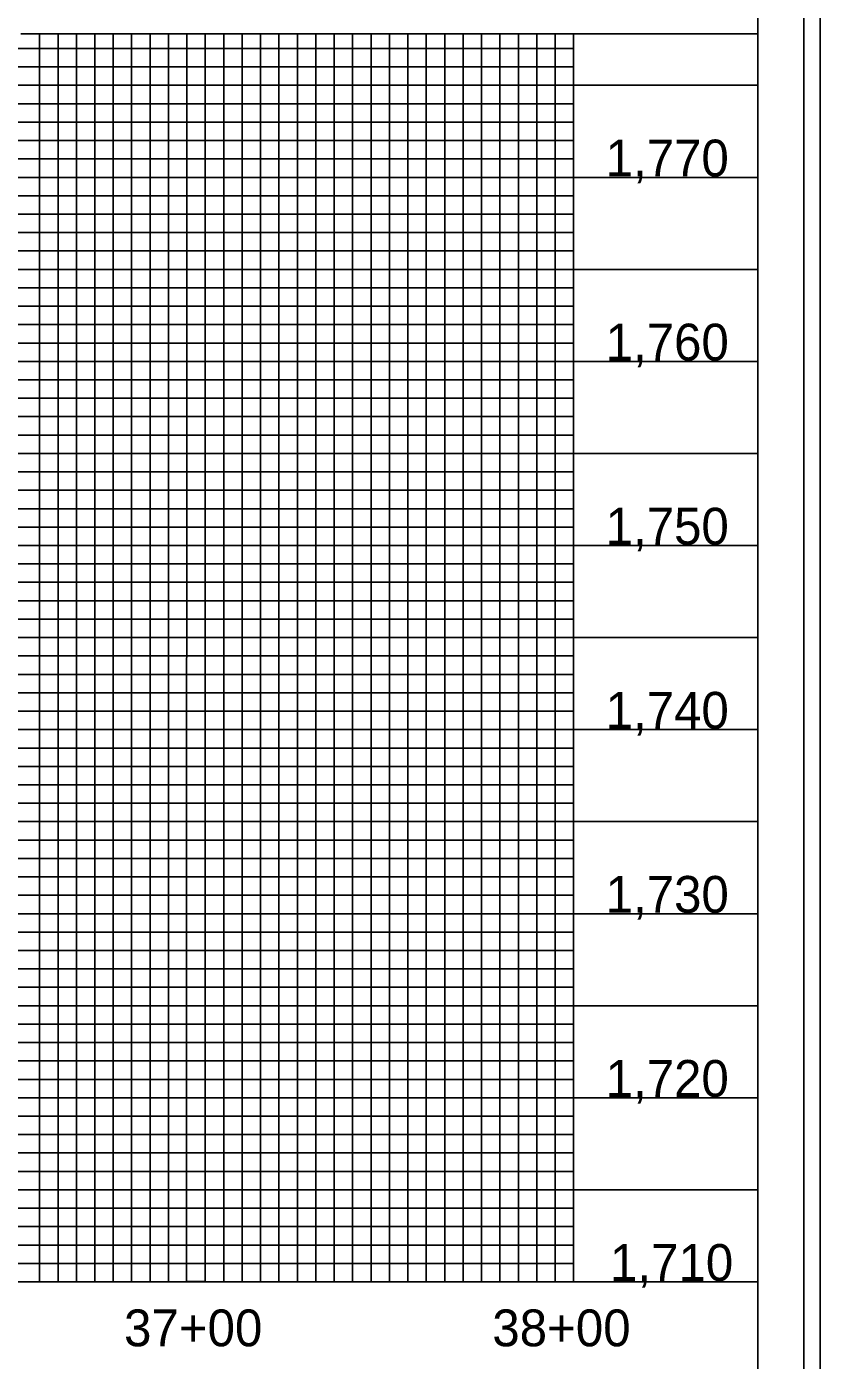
# Model space of a CAD drawing. Extents: x 497599 to 513368, y 404140 to 476034.
# Drawn here: x 507160.2 to 507375.7, y 439314.8 to 439677.1 of the extents above; entities that cross this region are included whole.
import ezdxf

# ---------------------------------------------------------------- set-up
doc = ezdxf.new("R2010")
doc.units = 0
for name, color, linetype in [('Exist Vertical Profile Vertical Axis Label', 7, 'Continuous'), ('Sheet DOT Grid CELL', 7, 'Continuous'), ('Sheet Plot Border Inside CELL', 7, 'Continuous'), ('Sheet Plot Border Outside CELL', 7, 'Continuous'), ('Sheet Profile CELL', 7, 'Continuous'), ('Sheet Profile Grid Major CELL', 7, 'Continuous'), ('Sheet Profile Grid Middle CELL', 7, 'Continuous'), ('Sheet Profile Grid Minor CELL', 7, 'Continuous'), ('Sheet Sticker Exception Certification CELL', 7, 'Continuous')]:
    doc.layers.add(name, color=color, linetype=linetype)

msp = doc.modelspace()

# ---------------------------------------------------------------- linework, layer by layer
at = {"layer": 'Sheet DOT Grid CELL'}
for p, q in [((507208.68, 439336.14), (507208.68, 439675.09)), ((507258.68, 439336.14), (507258.68, 439675.09)), ((507308.68, 439336.14), (507308.68, 439675.09)), ((507358.68, 439636.14), (505858.68, 439636.14)), ((507358.68, 439586.14), (505858.68, 439586.14)), ((507358.68, 439536.14), (505858.68, 439536.14)), ((507358.68, 439486.14), (505858.68, 439486.14)), ((507358.68, 439436.14), (505858.68, 439436.14)), ((507358.68, 439386.14), (505858.68, 439386.14))]:
    msp.add_line(p, q, dxfattribs=at)
at = {"layer": 'Sheet Plot Border Inside CELL'}
msp.add_lwpolyline([(505704.68, 438783.59), (507371.18, 438783.59), (507371.18, 439838.69), (505704.68, 439838.69)], close=True, dxfattribs=at)
at = {"layer": 'Sheet Plot Border Outside CELL'}
msp.add_lwpolyline([(505691.68, 438761.14), (507375.68, 438761.14), (507375.68, 439861.14), (505691.68, 439861.14)], close=True, dxfattribs=at)
at = {"layer": 'Sheet Profile CELL'}
msp.add_line((505858.68, 439336.14), (507358.68, 439336.14), dxfattribs=at)
msp.add_lwpolyline([(507358.68, 439836.14), (505858.68, 439836.14), (505858.68, 438786.14), (507358.68, 438786.14)], close=True, dxfattribs=at)
at = {"layer": 'Sheet Profile Grid Major CELL'}
for points in [[(507308.68, 439675.09), (507308.68, 439336.14), (507358.68, 439336.14), (507358.68, 439686.14)], [(507208.68, 439675.09), (507208.68, 439336.14), (507258.68, 439336.14), (507258.68, 439336.14), (507258.68, 439675.09)], [(507358.68, 439636.14), (505858.68, 439636.14), (505858.68, 439586.14), (507358.68, 439586.14)], [(507358.68, 439536.14), (505858.68, 439536.14), (505858.68, 439486.14), (507358.68, 439486.14)], [(507358.68, 439436.14), (505858.68, 439436.14), (505858.68, 439436.14), (505858.68, 439386.14), (507358.68, 439386.14)]]:
    msp.add_lwpolyline(points, dxfattribs=at)
at = {"layer": 'Sheet Profile Grid Middle CELL'}
for points in [[(506683.68, 439836.14), (506733.68, 439836.14), (506733.68, 439336.14), (506783.68, 439336.14), (506783.68, 439836.14), (506833.68, 439836.14), (506833.68, 439336.14), (506883.68, 439336.14), (506883.68, 439836.14), (506933.68, 439836.14), (506933.68, 439336.14), (506983.68, 439336.14), (506983.68, 439836.14), (507033.68, 439836.14), (507033.68, 439336.14), (507083.68, 439336.14), (507083.68, 439836.14), (507133.68, 439836.14), (507133.68, 439336.14), (507183.68, 439336.14), (507183.68, 439675.09)], [(507183.68, 439598.94), (507183.68, 439336.14), (507233.68, 439336.14), (507233.68, 439675.09)], [(507233.68, 439598.94), (507233.68, 439336.14), (507283.68, 439336.14), (507283.68, 439675.09)], [(507358.68, 439661.14), (505858.68, 439661.14), (505858.68, 439611.14), (507183.68, 439611.14)], [(507183.68, 439611.14), (507358.68, 439611.14)], [(507358.68, 439561.14), (505858.68, 439561.14), (505858.68, 439511.14), (507358.68, 439511.14)], [(507358.68, 439461.14), (505858.68, 439461.14), (505858.68, 439411.14), (507358.68, 439411.14)], [(507358.68, 439361.14), (505858.68, 439361.14)]]:
    msp.add_lwpolyline(points, dxfattribs=at)
at = {"layer": 'Sheet Profile Grid Minor CELL'}
for p, q in [((505908.68, 439671.14), (507308.68, 439671.14)), ((507308.68, 439651.14), (505908.68, 439651.14)), ((505908.68, 439646.14), (507308.68, 439646.14)), ((507308.68, 439626.14), (505908.68, 439626.14)), ((505908.68, 439621.14), (507308.68, 439621.14)), ((507308.68, 439601.14), (505908.68, 439601.14)), ((505908.68, 439596.14), (507308.68, 439596.14)), ((507308.68, 439591.14), (505908.68, 439591.14)), ((505908.68, 439581.14), (507308.68, 439581.14)), ((507308.68, 439576.14), (505908.68, 439576.14)), ((505908.68, 439571.14), (507308.68, 439571.14)), ((507308.68, 439566.14), (505908.68, 439566.14)), ((505908.68, 439556.14), (507308.68, 439556.14)), ((507308.68, 439551.14), (505908.68, 439551.14)), ((505908.68, 439546.14), (507308.68, 439546.14)), ((507308.68, 439541.14), (505908.68, 439541.14)), ((505908.68, 439531.14), (507308.68, 439531.14)), ((507308.68, 439526.14), (505908.68, 439526.14)), ((505908.68, 439521.14), (507308.68, 439521.14)), ((507308.68, 439516.14), (505908.68, 439516.14)), ((505908.68, 439506.14), (507308.68, 439506.14)), ((507308.68, 439501.14), (505908.68, 439501.14)), ((505908.68, 439496.14), (507308.68, 439496.14)), ((507308.68, 439491.14), (505908.68, 439491.14)), ((505908.68, 439481.14), (507308.68, 439481.14)), ((507308.68, 439476.14), (505908.68, 439476.14)), ((505908.68, 439471.14), (507308.68, 439471.14)), ((507308.68, 439466.14), (505908.68, 439466.14)), ((505908.68, 439456.14), (507308.68, 439456.14)), ((507308.68, 439451.14), (505908.68, 439451.14)), ((507308.68, 439446.14), (505908.68, 439446.14)), ((507308.68, 439441.14), (505908.68, 439441.14)), ((505908.68, 439431.14), (507308.68, 439431.14)), ((507308.68, 439426.14), (505908.68, 439426.14)), ((505908.68, 439421.14), (507308.68, 439421.14)), ((507308.68, 439416.14), (505908.68, 439416.14)), ((505908.68, 439406.14), (507308.68, 439406.14)), ((507308.68, 439401.14), (505908.68, 439401.14)), ((505908.68, 439396.14), (507308.68, 439396.14)), ((507308.68, 439391.14), (505908.68, 439391.14)), ((505908.68, 439381.14), (507308.68, 439381.14)), ((507308.68, 439376.14), (505908.68, 439376.14)), ((505908.68, 439371.14), (507308.68, 439371.14)), ((507308.68, 439366.14), (505908.68, 439366.14)), ((505908.68, 439356.14), (507308.68, 439356.14)), ((507308.68, 439351.14), (505908.68, 439351.14)), ((505908.68, 439346.14), (507308.68, 439346.14))]:
    msp.add_line(p, q, dxfattribs=at)
for points in [[(507163.68, 439675.09), (507163.68, 439336.14), (507168.68, 439336.14), (507168.68, 439675.09)], [(507173.68, 439675.09), (507173.68, 439336.14), (507178.68, 439336.14), (507178.68, 439675.09)], [(507188.68, 439675.09), (507188.68, 439336.14), (507188.68, 439336.14), (507193.68, 439336.14), (507198.68, 439336.14), (507198.68, 439675.09)], [(507193.68, 439675.09), (507193.68, 439336.14)], [(507203.67, 439675.09), (507203.58, 439336.19), (507208.58, 439336.19), (507213.68, 439336.14), (507213.68, 439675.09)], [(507213.68, 439598.94), (507213.68, 439336.14), (507218.68, 439336.14), (507218.68, 439675.09)], [(507223.68, 439675.09), (507223.68, 439336.14), (507228.68, 439336.14), (507228.68, 439675.09)], [(507238.68, 439675.09), (507238.68, 439336.14), (507243.68, 439336.14), (507243.68, 439675.09)], [(507248.68, 439675.09), (507248.68, 439336.14), (507253.68, 439336.14), (507253.68, 439675.09)], [(507263.68, 439675.09), (507263.68, 439336.14), (507268.68, 439336.14), (507268.68, 439675.09)], [(507273.68, 439675.09), (507273.68, 439336.14), (507278.68, 439336.14), (507278.68, 439675.09)], [(507288.68, 439675.09), (507288.68, 439336.14), (507293.68, 439336.14), (507293.68, 439675.09)], [(507298.68, 439675.09), (507298.68, 439336.14), (507303.68, 439336.14), (507303.68, 439675.09)], [(507308.68, 439666.14), (505908.68, 439666.14), (505908.68, 439656.14), (507308.68, 439656.14)], [(507308.68, 439641.14), (505908.68, 439641.14), (505908.68, 439631.14), (507308.68, 439631.14)], [(507308.68, 439616.14), (505908.68, 439616.14), (505908.68, 439606.14), (507308.68, 439606.14)], [(507308.68, 439341.14), (505908.68, 439341.14)]]:
    msp.add_lwpolyline(points, dxfattribs=at)
at = {"layer": 'Sheet Sticker Exception Certification CELL'}
for p, q in [((507358.67, 439698.58), (507358.67, 439675.08)), ((507358.67, 439698.58), (507358.67, 439675.08)), ((507358.67, 439675.09), (507158.63, 439675.09)), ((507358.67, 439675.09), (507158.63, 439675.09))]:
    msp.add_line(p, q, dxfattribs=at)

# ---------------------------------------------------------------- texts
at = {"layer": 'Exist Vertical Profile Vertical Axis Label'}
for s, p in [('1,770', (507317.37, 439636.39)), ('1,760', (507317.37, 439586.39)), ('1,750', (507317.37, 439536.39)), ('1,740', (507317.37, 439486.39)), ('1,730', (507317.37, 439436.39)), ('1,720', (507317.37, 439386.39)), ('1,710', (507318.57, 439336.39)), ('37+00', (507186.61, 439318.64)), ('38+00', (507286.61, 439318.64))]:
    msp.add_text(s, height=10, dxfattribs=at).set_placement(p)

doc.saveas('drawing.dxf')
